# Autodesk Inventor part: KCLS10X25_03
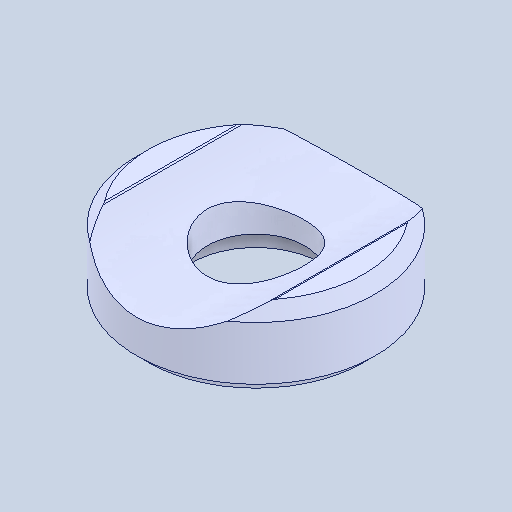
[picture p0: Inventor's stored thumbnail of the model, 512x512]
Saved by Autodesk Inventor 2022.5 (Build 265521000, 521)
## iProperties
Created: 2024-08
Part Number: KCLS10X25_03
Material: 一般
Document SubType Name: Modeling
Designer: ImaoCorp
Density: 1 g/cm^3
Appearance: 既定
Author: ImaoCorp
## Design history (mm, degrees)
feature "KCLS10X25_03"
node "ソリッド1"
